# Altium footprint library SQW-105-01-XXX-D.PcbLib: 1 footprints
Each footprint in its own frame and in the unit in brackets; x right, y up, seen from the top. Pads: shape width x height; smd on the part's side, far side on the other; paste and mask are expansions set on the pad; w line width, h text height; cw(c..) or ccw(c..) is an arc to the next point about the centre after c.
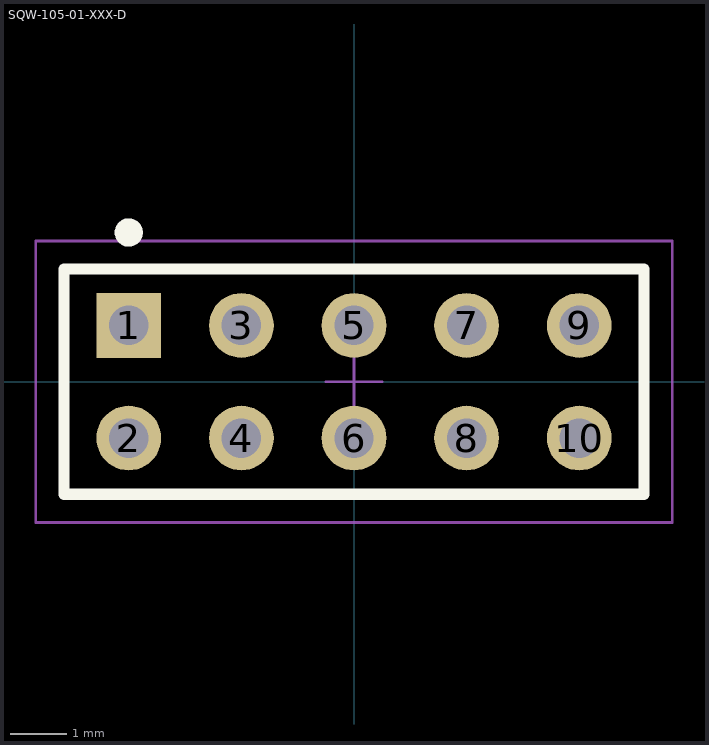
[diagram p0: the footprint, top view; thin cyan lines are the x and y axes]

## SQW-105-01-XXX-D [mm] "2.00mm pitch, 10 pin, socket strip; double row, SMT"
height 6.35
pads (10):
  rect 1.15x1.15 / inner round 1.15 / far side rect 1.15x1.15 hole 0.7 mask+0: 1(-4,1)
  round 1.15 hole 0.7 mask+0: 2(-4,-1) 3(-2,1) 4(-2,-1) 5(0,1) 6(0,-1) 7(2,1) 8(2,-1) 9(4,1) 10(4,-1)
Top Overlay:
  circle w0.25: c-4,2.65 r0.125
  lines w0.2: -5.15,-2 5.15,-2 5.15,2 -5.15,2 -5.15,-2
Mechanical 12:
  lines w0.001: -5.15,-2 5.15,-2 5.15,2 -5.15,2 -5.15,-2
Mechanical 13:
  lines w0.1: -5.15,-2 5.15,-2 5.15,2 -5.15,2 -5.15,-2
  text ".Designator" at 0,-0.127 h1.52
Mechanical 15:
  lines w0.05: -0.5,0 0.5,0 ; 0,-0.5 0,0.5 ; -5.65,-2.5 5.65,-2.5 5.65,2.5 -5.65,2.5 -5.65,-2.5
